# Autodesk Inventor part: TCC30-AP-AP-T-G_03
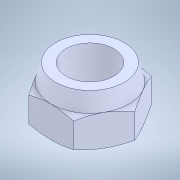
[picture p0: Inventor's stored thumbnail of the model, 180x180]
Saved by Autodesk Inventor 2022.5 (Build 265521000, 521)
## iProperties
Created: 2023-09
Part Number: TCC30-AP-AP-T-G_03
Material: 一般
Document SubType Name: Modeling
Designer: ImaoCorp
Density: 1 g/cm^3
Appearance: 既定
Author: ImaoCorp
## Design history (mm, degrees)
feature "TCC30-AP-AP-T-G_03"
node "ソリッド1"
